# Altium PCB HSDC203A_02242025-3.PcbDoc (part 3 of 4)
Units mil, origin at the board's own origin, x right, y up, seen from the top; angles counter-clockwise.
Board outline 5612.98 x 3012.39 mil, 6 copper layers (Top Layer, GND1, Signal1, Power, GND2, Bottom Layer), stack 60.4 mil thick; 301 components, 211 nets, 1107 pads, 249 vias.
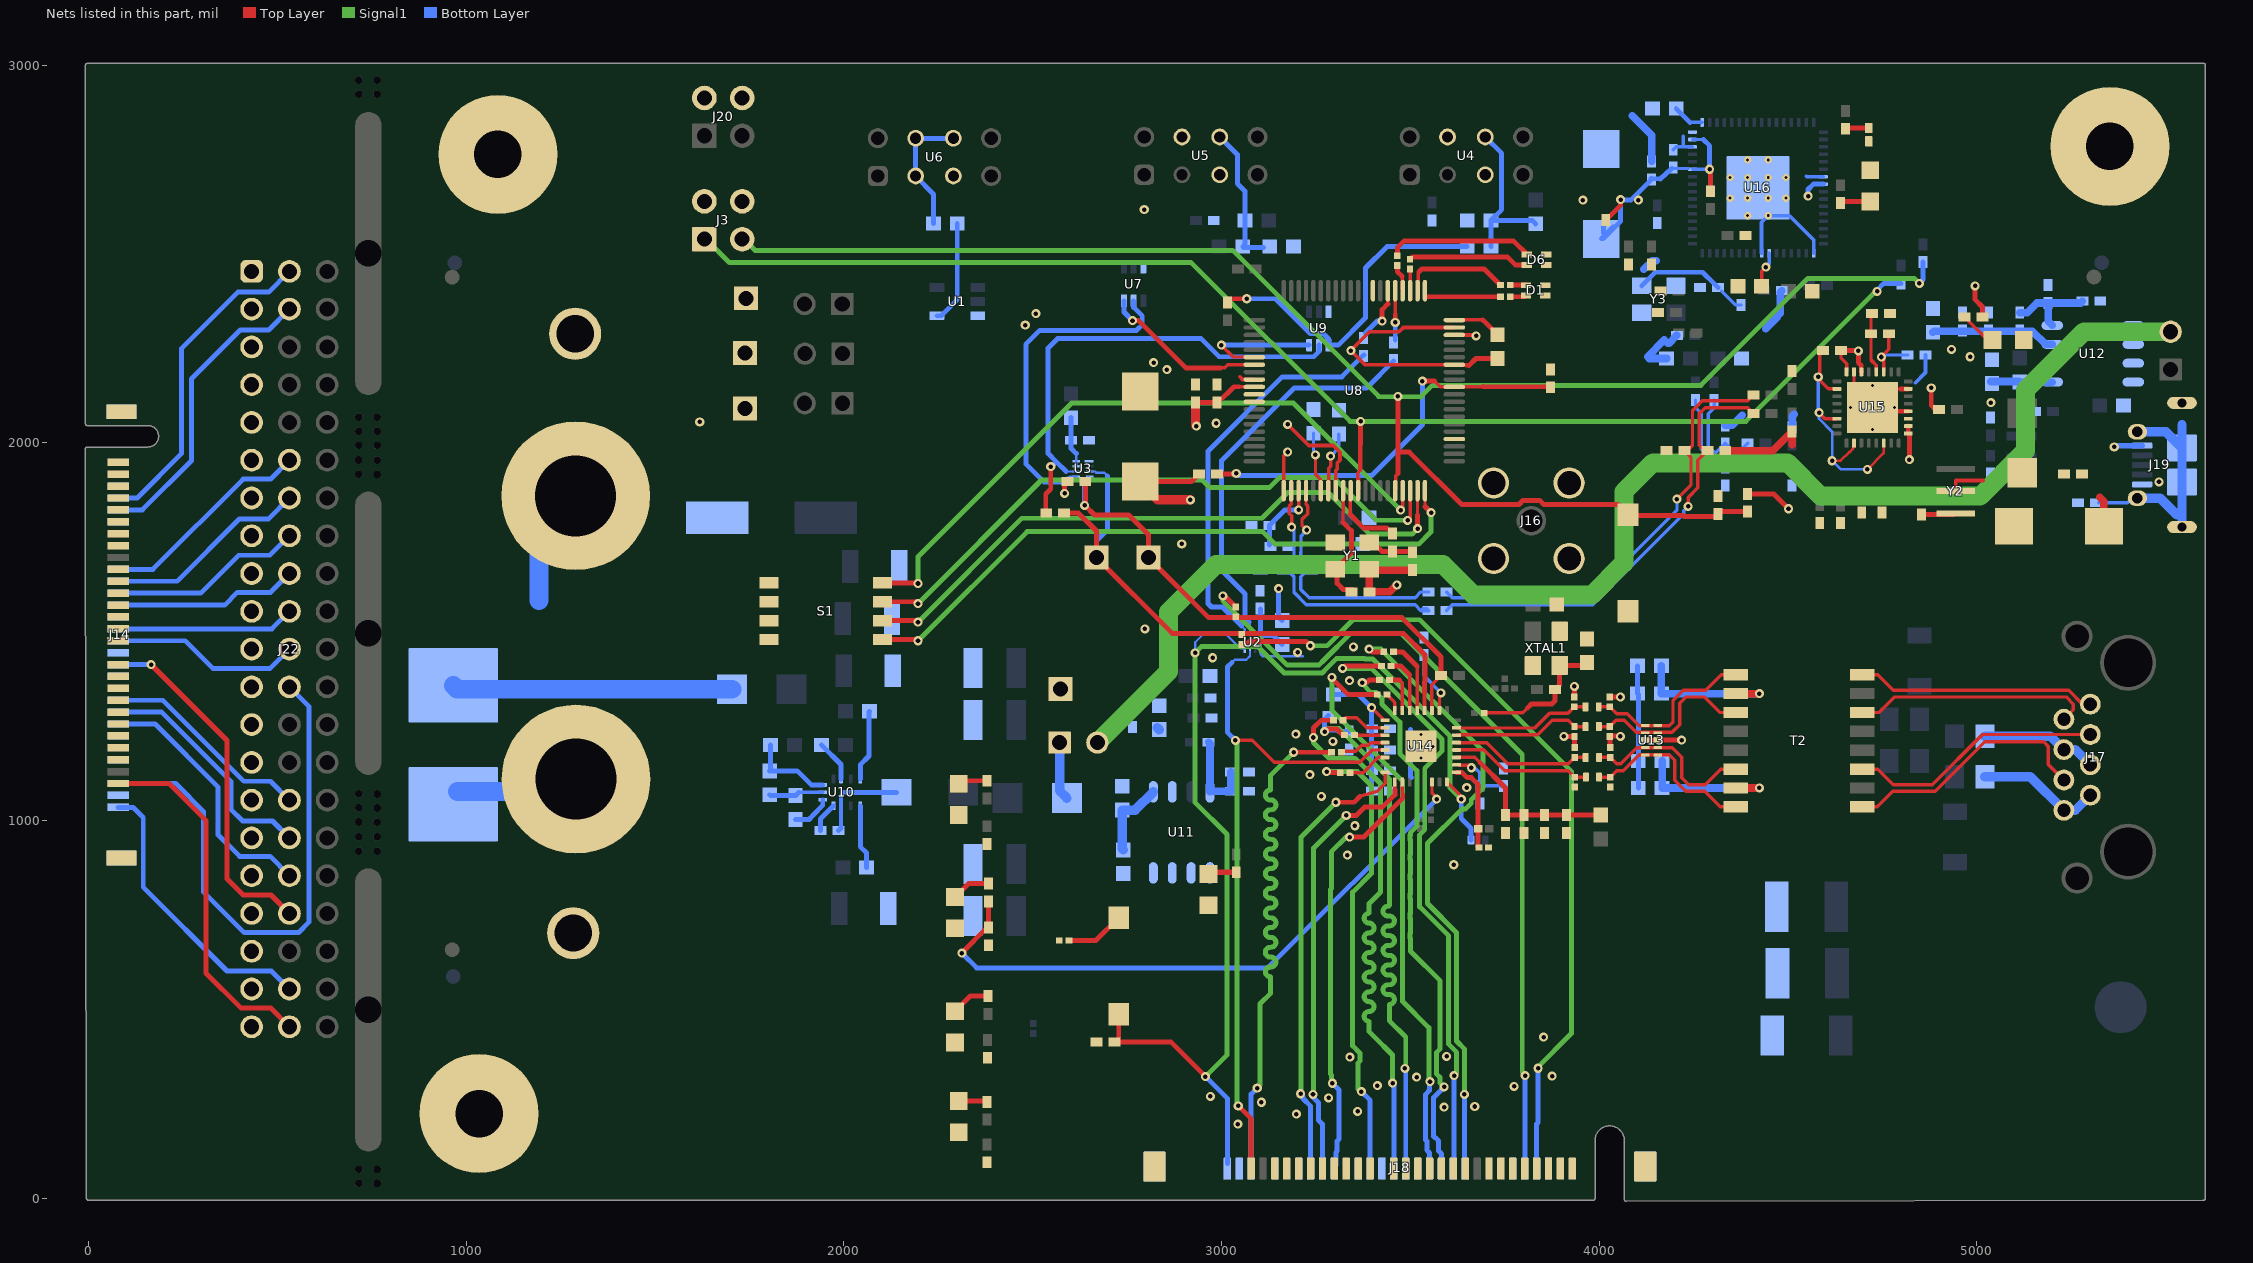
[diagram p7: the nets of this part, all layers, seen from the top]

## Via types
v1: diameter 24, hole 12, Top Layer to Bottom Layer, tented both sides, 227 vias
v2: diameter 19.68, hole 7.87, Top Layer to Bottom Layer, 17 vias
v3: diameter 19.68, hole 7.87, Top Layer to Bottom Layer, tented both sides, 5 vias

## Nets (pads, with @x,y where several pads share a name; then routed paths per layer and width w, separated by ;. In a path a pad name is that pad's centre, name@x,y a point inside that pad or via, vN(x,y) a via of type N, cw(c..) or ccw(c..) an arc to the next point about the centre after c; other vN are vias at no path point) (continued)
GND: C1.2 C2.2 C3.2 C4.2 C5.2 C6.2 C7.2 C8.2 C9.2 C10.2 C11.1 C12.2 C13.2 C14.2 C15.2 C16.2 C17.1 C18.2 C19.2 C20.2 C21.2 C22.2 C24.2 C25.2 C26.2 C27.2 C28.2 C29.2 C30.2 C31.2 C32.2 C33.2 C34.2 C35.2 C36.2 C37.2 C38.2 C39.2 C40.2 C41.2 C42.2 C43.2 C44.2 C45.2 C46.2 C47.2 C48.2 C49.2 C50.2 C51.2 C52.2 C53.2 C54.2 C55.2 C56.2 C57.2 C60.2 C61.1 C62.2 C63.1 C64.2 C65.1 C66.2 C67.2 C68.2 C69.2 C70.1 C71.1 C72.2 C73.2 C74.2 C75.2 C76.2 C77.2 C78.2 C79.2 C80.2 C81.2 C82.2 C83.2 C84.2 C85.2 C86.2 C87.2 C89.2 C90.2 C91.2 C92.2 C93.2 C94.2 C95.2 C96.2 C97.2 C98.2 D1.3 D1.4 D4.1 D5.2 D6.3 D6.4 H1.1 H2.1 H3.1 J3.2 J3.4 J5.1 J10.1 J11.1 J12.1 J13.1 J16.2 J16.3 J16.4 J16.5 J18.1 J18.3 J18.5 J18.6 J18.7 J18.9 J18.11 J18.12 J18.13 J18.15 J18.19 J18.21 J18.23 J18.25 J18.27 J18.28 J18.29 J18.31 J18.34 J18.35 J18.37 J18.38 J18.39 J18.41 J18.43 J18.45 J18.47 J18.48 J18.49 J18.51 J18.52 J18.58 J18.MP1 J18.MP2 J18.MP3 J18.MP4 J19.5 J20.2 J20.4 J21.1 LD1.2 LD2.2 LD3.2 LD4.2 LD5.2 LD6.2 R12.1 R21.2 R26.1 R30.1 R31.1 R35.1 R36.1 R48.1 R49.1 R50.1 R51.2 R54.1 R56.2 R59.1 R60.1 R69.1 R70.1 R73.1 R74.1 R75.2 R81.1 R82.1 R83.1 R84.1 R85.1 R91.1 R92.1 R115.1 S1.5 S1.6 S1.7 S1.8 S2.1 U1.3 U2.1 U3.1 U4.3 U4.7 U5.3 U5.7 U6.3 U7.3 U8.14 U8.19 U8.49 U8.61 U8.68 U9.3 U10.1 U10.6 U10.11 U11.5 U11.6 U11.7 U11.8 U12.5 U12.6 U12.7 U12.8 U13.3@4122.24,1213.15 U13.8@4155.12,1213.15 U14.33 U15.7 U15.27 U15.28 U15.31 U15.33 U16.14 U16.16 U16.39 U16.49 U16.56 U16.65 XTAL1.2 XTAL1.4 Y1.2 Y1.4 Y2.2 Y3.2 Y3.4 | length 4770.6
  Top Layer w9: U15.7@4674.52,2188.42 4674.52,2143.14 v2(4723.73,2093.93)
  Top Layer w10: 3048.53,2175.2 3055.75,2167.98 U8.49@3086.92,2167.98 U8.49@3086.92,2168.23 ; U8.61@3164.67,1873.69 3164.67,1965.87 v1(3174.9,1976.1) ; v1(3174.9,2049.48) 3231,1993.38 3295.81,1993.38 3313.85,1975.33 3313.85,1954.73 3306.35,1947.23 3306.35,1931.03 3302.47,1927.15 U8.68@3302.47,1873.69 ; U8.14@3616.45,2206.44 3648.58,2206.44 3648.58,2204.72 3654.83,2204.72 3652.21,2207.35 U8.14@3616.45,2207.35 3379.77,2207.35 v1(3342.34,2244.78) 3391.95,2294.4 3470.25,2294.4 3481.63,2305.77 U8.19@3616.45,2305.77 ; Y2.2@4944.01,1872.28 4944.01,1900.9 5000.52,1900.9 5016.1,1900.9
  Top Layer w13: 3654.83,2204.72 3673.76,2223.66 C10.2@3731.07,2223.66 ; v1(3906.58,1223.19) C93.2@3934.63,1223.19 3935.04,1222.78 C95.2@3935.04,1193.47 ; C89.2@3934.22,1327.46 v1(3934.22,1355.51) ; C96.2@4028.12,1194.29 C94.2@4028.12,1223.19 ; C92.2@4028.12,1327.46 v1(4056.17,1327.46) ; C94.2@4028.94,1224.02 v1@4055.35,1224.02 ; U13.3@4122.24,1213.15 U13.8@4155.12,1213.15 v1(4218.39,1213.15) ; v2(4723.73,2093.93) 4733.57,2084.09 U15.28@4818.22,2084.09 ; 4797.1,2143.2 4797.16,2143.14 U15.31@4818.22,2143.14
  Top Layer w20: v1(3464.18,1624.02) 3445.82,1605.66 3391.39,1605.66 Y1.4@3391.39,1665.53 3393.36,1663.56 C8.2@3505.51,1663.56 ; R69.1@4333.77,1979.56 4459.75,1979.56 C68.2@4510.93,2030.74 4510.93,1995.31 ; 5325.73,1855.94 5336.07,1845.6 C64.2@5336.07,1779.04
  Bottom Layer w6: U2.1@3102.95,1456.3 3102.95,1440.55 3108.3,1435.21 3214.97,1435.21
  Bottom Layer w9: C87.2@4195.97,2776.21 4203.53,2783.78 4225.2,2783.78 ; 4222.75,2812.15 4222.75,2786.22 4225.2,2783.78 ; U16.14@4246.94,2783.78 4225.2,2783.78 ; 4548.12,2706 4549.08,2705.04 U16.39@4593.39,2705.04
  Bottom Layer w10: C26.2@1881,1075 U10.6@1944.28,1075 ; U16.56@4430.01,2502.28 4430.01,2584.17 v2(4447.53,2601.69) 4503.39,2601.69 4567.8,2537.28 U16.49@4567.8,2502.28 ; 4837.03,2159.48 4863.78,2186.23 C77.2@4863.78,2232.88
  Bottom Layer w13: R26.1@1803.78,1068.75 1806.34,1066.19 C26.2@1872.19,1066.19 C26.2@1881,1075 ; U10.1@2043.69,1039.56 2043.69,931.17 2060.48,914.39 2060.48,875.76 C22.2@2060.43,875.7 ; U10.11@2043.69,1110.43 2043.69,1148.31 2066.73,1171.35 2066.73,1288.48 C20.2@2067.83,1289.57 ; 3500.71,1241.37 3500.71,1116.63 3503.54,1113.8 ; C45.2@4101.54,1410.13 C46.2@4101.54,1336.54 4103.45,1334.62 C55.2@4103.45,1158.23 C56.2@4103.45,1086.54
  Bottom Layer w20: 4088,2866 4138.89,2815.11 C86.2@4138.89,2745.31 ; 4118.39,2459.57 4141.11,2482.29 4150.7,2482.29 ; 4172.66,2272.89 4128,2228.24 4132.58,2223.66 C75.2@4178.55,2223.66 ; 4181.37,2264.18 4185.25,2264.18 R81.1@4205.75,2284.68 ; R74.1@4333.77,2046.49 4351.91,2046.49 4378.37,2072.95 ; 4441.45,2302.71 4471.21,2332.48 4471.21,2336.42 4478.71,2343.92 4478.71,2399.05 C91.2@4483.16,2403.49 ; C73.2@4510.93,2042.55 4510.93,2070.79 4516.16,2076.02
  Bottom Layer w50: 1192.52,1582.71 1192.52,1790.19 J21.1@1251.57,1849.25
  other v1: 3043.58,196.52 3198.43,223.38 3360.6,230.28 3589.14,241.73 3670.45,243.31 3105.71,254.57 3283.63,266.11 2970.51,270.04 3774.94,296.33 3412.43,298.46 3516.65,321.11 3875.03,323.88 3339.8,374.02 3596.08,375.94 3852.73,426.8 3614.79,883.31 3333.22,908.7 3352.94,986.57 3264.29,1064.13 3649.34,1087.43 3234.16,1121.89 3294.96,1209.99 4056.17,1223.19 3197.17,1229.42 3338.89,1371.06 2976.67,1431.3 3201.55,1445.78 3348.87,1460.19 2797.29,1507.84 2894.81,1732.92 5482,1897 2985.67,2052.31 1618.66,2055.59 5037.01,2106.69 2855.2,2194 2820.14,2212.83 2480.36,2311.94 2508.7,2342.61 2795.44,2617.86
  other v2: 4723.73,2035.86 4665.66,2093.93 4781.8,2093.93 4723.73,2152 4392.8,2601.69 4346.34,2648.15 4392.8,2648.15 4447.53,2648.15 4493.98,2648.15 4346.34,2702.87 4392.8,2702.87 4447.53,2702.87 4493.98,2702.87 4392.8,2749.33 4447.53,2749.33
  other v3: 3527.82,1165.52 3496.33,1197.01 3527.82,1197.01 3559.32,1197.01 3527.82,1228.51
GND_EXT: J14.1 J14.3 J14.5 J14.6 J14.7 J14.9 J14.11 J14.12 J14.13 J14.15 J14.19 J14.21 J14.23 J14.25 J14.27 J14.28 J14.29 J14.31 J14.34 J14.35 J14.37 J14.38 J14.39 J14.41 J14.43 J14.45 J14.47 J14.48 J14.49 J14.51 J14.52 J14.58 J14.MP1 J14.MP2 J14.MP3 J14.MP4 J22.1 J22.4 J22.7 J22.10 J22.13 J22.16 J22.19 J22.22 J22.25 J22.28 J22.31 J22.34 J22.37 J22.40 J22.43 J22.46 J22.49 J22.52 J22.55 J22.58 J22.61
HUB_D1_N: R63.2 R67.1 R70.2 | length 1191
  Top Layer w9: v1(4205.82,1851.61) 4242.87,1888.66 4242.87,1962.19 R70.2@4225.5,1979.56 4230,1984.06 4237.26,1984.06 4247.01,1993.82 4247.01,2085.53 4273.08,2111.59 4392.97,2111.59 R67.1@4408.57,2127.2 R67.1@4408.46,2127.31
  Bottom Layer w9: R63.2@3595.58,1605.55 3611.19,1589.94 3973.67,1589.94 4205.82,1822.08 v1(4205.82,1851.61)
HUB_D1_P: R66.2 R68.1 R69.2 | length 1193.6
  Top Layer w9: v1(4235.34,1831.92) 4235.34,1855.68 4260.87,1881.21 4260.87,1953.91 R69.2@4286.52,1979.56 4282.02,1984.06 4274.77,1984.06 4265.01,1993.82 4265.01,2078.07 4280.54,2093.59 4392.97,2093.59 R68.1@4408.57,2077.99
  Bottom Layer w9: R66.2@3595.58,1556.33 3611.19,1571.94 3982.82,1571.94 4223.82,1812.94 ; 4223.82,1814.63 4223.82,1820.4 v1(4235.34,1831.92)
HUB_D2_N: R71.1 R74.2 R76.2 | length 268.5
  Bottom Layer w9: R76.2@4304.24,2113.42 4304.24,2093.17 4288.64,2077.57 4288.64,1991.18 4304.04,1975.77 4310.29,1975.77 R74.2@4333.77,1999.25 4357.25,1975.77 4369.15,1975.77 R71.1@4392.82,1999.44
HUB_D2_P: R72.1 R73.2 R80.2 | length 292.7
  Bottom Layer w9: R80.2@4255.03,2113.42 4255.03,2093.17 4270.64,2077.57 4270.64,1983.72 4296.59,1957.77 4310.29,1957.77 R73.2@4333.77,1934.29 4357.25,1957.77 4369.69,1957.77 4379.58,1947.88 R72.1@4392.82,1947.88
LED_0: R54.2 R55.1 U14.30 | length 1679.4
  Top Layer w9: U14.30@3557.35,1102.52 3557.39,1072.4 3571.71,1058.08 3570.87,1057.24 v1(3569.72,1057.24)
  Top Layer w13: v1(2312.37,649.61) 2380.26,717.49 R54.2@2383.24,717.49 R55.1@2383.24,786.39
  Bottom Layer w13: v1(2312.37,649.61) 2351.74,610.24 3122.72,610.24 v1(3569.72,1057.24)
MCU_VCC: C13.1 C14.1 C15.1 C39.1 C40.1 C41.1 C77.1 C85.1 C86.1 C87.1 R1.2 R22.1 R23.1 R33.2 R34.2 R61.2 R62.2 R79.2 R90.2 R93.2 U8.18 U8.50 U12.3 U15.3 U15.6 U15.8 U15.25 U15.26 U16.11 U16.15 U16.40 | length 2510.9
  Top Layer w9: 3046.32,2148.85 U8.50@3086.92,2148.85 ; R62.2@4649.63,2245.23 4640.23,2235.83 4640.23,2223.85 4654.83,2209.25 U15.8@4654.83,2188.42 ; U15.3@4753.26,2188.42 4753.26,2221.19 v1(4746.86,2227.59) 4766.84,2247.57 R79.2@4766.84,2289.18
  Top Layer w10: U8.18@3616.45,2286.65 3617.35,2285.74 3671.93,2285.74 v1(3674.21,2283.46)
  Top Layer w13: C13.1@2784.75,1895.89 C13.1@2784.75,1897.97 2921.16,1897.97 R23.1@2940.55,1917.36 ; v1@2931.18,2046.95 v1(2933.41,2044.72) ; C15.1@2931.18,2107.62 C14.1@2987.94,2107.62 2991.84,2107.62 3033.07,2148.85 3046.32,2148.85 ; R90.2@4017.32,2590.11 4056.69,2629.48 v1(4056.69,2644.16) ; v1(4292.21,2724.72) 4294.4,2722.53 R93.2@4294.4,2666.57 ; R22.1@4392.82,1865.39 4461.56,1865.39 v1(4501.09,1825.86) ; R62.2@4640.23,2245.23 4649.63,2245.23 4684.47,2245.23 v1(4686.07,2243.62) 4686.07,2212.77 4693.81,2205.03 4693.81,2188.81 U15.6@4694.2,2188.42 ; U15.26@4818.22,2044.72 U15.25@4818.22,2025.03 4821.17,2022.08 v1(4821.17,1955.8) ; v1(4879.04,2145.67) 4879.04,2099.76 R61.2@4890.22,2088.58 ; v1(4995.19,2415.9) 4995.19,2379.49 5014.72,2359.96 R34.2@5014.72,2333.36
  Top Layer w25: C13.1@2784.75,1895.89 2831.2,1849.44 v1(2917.38,1849.44) ; v1@2931.18,2046.95 C15.1@2931.18,2107.62
  Bottom Layer w9: C87.1@4192.42,2726.6 U16.11@4236.45,2726.6 ; U16.11@4246.94,2724.72 v1(4292.21,2724.72) ; U16.15@4246.94,2803.46 4275.69,2803.46 ; v1(4746.86,2227.59) 4752.15,2232.88 C77.1@4816.54,2232.88
  Bottom Layer w13: v1(3151.18,1614.17) 3151.18,1539.27 R1.2@3160.92,1529.53 ; C85.1@4011.47,2556.03 C85.1@4011.47,2571.71 ; C85.1@4037.01,2572.02 C85.1@4005.57,2540.58 4010.35,2540.58 4056.69,2586.93 4056.69,2642.95 4083.77,2642.95 C86.1@4138.89,2698.07 ; C86.1@4137.06,2700.08 4138.98,2699.98 4161.78,2698.85 C87.1@4192.42,2726.6 ; 4275.69,2803.46 4292.21,2786.94 v1(4292.21,2724.72) ; v1(4552.81,2653.76) 4552.81,2671.04 4567.12,2685.35 U16.40@4593.39,2685.35
  Bottom Layer w20: C41.1@4883.46,2293.31 4886.48,2296.33 5146.76,2296.33 5181.86,2261.22 U12.3@5199.41,2261.22
  other v1: 4981.89,2228.24 4932.68,2247.57 3956.51,2643.24 4103.45,2643.24
MDC: J1.1 R18.1 R109.1 U3.3 U14.12 | length 1579.9
  Top Layer w10: U14.12@3537.67,1291.5 3537.71,1338.58
  Top Layer w13: R109.1@2583.27,1814.44 2621.5,1814.44 2668.9,1767.04 2668.9,1720.85 J1.1@2685.56,1704.19 ; J1.1@2668.9,1696.58 2869.42,1496.06 3481.37,1496.06 3538.9,1438.53 3538.9,1368.86 3537.77,1367.73 3537.77,1338.64 3537.71,1338.58
  Bottom Layer w6: U3.3@2651.18,1924.44 2651.44,1924.19 2665.32,1924.19 2668.25,1921.26 2689.9,1921.26 2698.43,1912.74
  Bottom Layer w13: J1.1@2668.9,1696.58 2668.9,1741.32 2698.43,1770.84 2698.43,1912.74
MDC_EXT: J14.8 J22.2 | length 865.1
  Bottom Layer w13: J14.8@78.74,1854.33 128.88,1854.33 247.01,1972.46 247.01,2250.74 395.52,2399.25 477.17,2399.25 J22.2@532.28,2454.36
MDC_LVL: R109.2 U3.6 U9.5 | length 1298
  Top Layer w13: R109.2@2536.02,1814.44 2534.64,1815.82 2534.64,1864.95 2547.92,1878.23 v1(2547.92,1937.45)
  Bottom Layer w6: 2588.55,1924.44 U3.6@2615.75,1924.44
  Bottom Layer w13: v1@2543.34,1935.44 2546.84,1935.44 2562.2,1950.79 ; 2588.55,1924.44 2562.2,1950.79 ; U9.5@3257.7,2258.86 3257.7,2241.48 3244.54,2228.33 3239.85,2228.33 3239.76,2228.24 3239.68,2228.33 2993.8,2228.33 2945.89,2276.24 2565.74,2276.24 2540.94,2251.44 2540.94,1972.05 2562.2,1950.79
MDC_MSP: U8.46 U9.6 | length 332.5
  Top Layer w9: v1(2999.75,2258.86) 3031.02,2227.59 U8.46@3086.92,2227.59
  Bottom Layer w13: v1(2999.75,2258.86) U9.6@3232.11,2258.86
MDC_S: J18.8 R18.2 | length 2154.6
  Top Layer w13: R18.2@3053.74,1466.54 3056.3,1469.09 3067.96,1469.09 3073.42,1474.55 3224.02,1474.55 v1(3235.34,1463.22)
  Signal1 w13: v1(3235.34,1463.22) 3279.57,1463.22 3348.28,1531.93 3524.73,1531.93 3926.24,1130.43 3926.24,436.48 v1@3834.25,344.5
  Bottom Layer w13: J18.8@3838.39,92.66 3834.25,96.8 3834.25,196.85 3838.39,200.98 v1(3838.39,344.5)
MDIO: J2.1 R19.1 R47.1 R110.1 U3.4 U14.11 | length 1435.8
  Top Layer w9: U14.11@3557.35,1291.5 3556.64,1292.25 3556.64,1359.91 R47.1@3581.01,1384.29
  Top Layer w13: R110.1@2639.37,1897.87 2639.37,1833.52 2663.68,1809.2 2754.21,1809.2 2806.69,1756.72 J2.1@2806.69,1696.58 2965.77,1537.51 3477.47,1537.51 3581.01,1433.96 R47.1@3581.01,1384.29
  Bottom Layer w13: v1(2637.4,1835.02) 2637.4,1895.83 2647.77,1906.2 2647.24,1906.73
MDIO_EXT: J14.10 J22.5 | length 800.9
  Bottom Layer w13: J14.10@78.74,1822.83 143,1822.83 273.16,1953 273.16,2170.12 402.3,2299.25 477.17,2299.25 J22.5@532.28,2354.36
MDIO_LVL: R110.2 U3.5 U7.5 | length 944.9
  Top Layer w13: v1(2584.68,1866.58) 2584.68,1890.43 R110.2@2592.13,1897.87
  Bottom Layer w6: 2580.32,1896.86 2591.1,1907.64 2595.51,1907.64 2598.53,1910.66 U3.5@2615.75,1910.66
  Bottom Layer w13: v1(2584.68,1866.58) 2584.68,1892.49 2580.32,1896.86 2529.65,1896.86 2481.89,1944.62 2481.89,2261.22 2518.91,2298.24 2775,2298.24 2790.11,2313.36 2790.11,2336.41 2767.32,2359.2 U7.5@2767.32,2376.57
MDIO_MSP: U7.6 U8.47 | length 439.8
  Top Layer w9: 2997.84,2198.93 3008.44,2198.93 3016.86,2207.35 U8.47@3086.92,2207.35
  Top Layer w13: v1(2764.31,2324.04) 2780.45,2324.04 2905.56,2198.93 2997.84,2198.93
  Bottom Layer w13: U7.6@2741.73,2376.57 2741.73,2346.62 v1(2764.31,2324.04)
MDIO_S: J18.10 R19.2 | length 2188.5
  Top Layer w13: v1(3003.54,1594.92) 3008.57,1594.92 R19.2@3037.71,1565.78
  Signal1 w13: v1@3805.81,324.8 3796.17,334.44 3796.17,1175.12 3475.23,1496.06 3341.93,1496.06 3272.59,1426.72 3257.64,1411.77 3174.4,1411.77 3003.54,1582.62 ; 3003.54,1582.62 v1(3003.54,1594.92) 3003.54,1582.62
  Bottom Layer w13: J18.10@3803.91,92.66 v1(3803.91,324.8)
MSP_PWDN: R10.2 U8.25 | length 131.5
  Top Layer w9: 3459.95,2340.58 U8.25@3459.95,2403.77
  Top Layer w13: v1(3459.95,2319.27) 3459.95,2340.58
  Bottom Layer w13: R10.2@3459.95,2272.31 v1(3459.95,2319.27)
MSP_RESET: R11.2 U8.26 | length 144.2
  Top Layer w9: 3440.27,2368.3 U8.26@3440.27,2403.77
  Top Layer w13: v1(3425.11,2322.83) 3425.11,2353.14 3440.27,2368.3
  Bottom Layer w13: R11.2@3381.21,2291.34 3412.71,2322.83 v1(3425.11,2322.83)
MSP_XIN: C7.1 U8.69 Y1.3 | length 313.3
  Top Layer w9: 3321.56,1790.51 3321.56,1818.4 3322.15,1818.99 U8.69@3322.15,1874.25
  Top Layer w13: 3321.56,1790.51 3343.98,1768.1 3343.98,1714.54 ; 3343.8,1708.24 3306.01,1670.45 3306.01,1628.22 3322.15,1612.08 C7.1@3347.75,1612.08
MSP_XOUT: R13.2 U8.70 | length 197.1
  Top Layer w9: 3340.43,1810.58 3340.43,1872.84 U8.70@3341.84,1874.25
  Top Layer w13: 3340.43,1810.58 3375.67,1775.34 3437.04,1775.34 R13.2@3452.37,1760.02
NetC3_1: C3.1 R3.1 R6.2 U4.6 | length 441.9
  Bottom Layer w13: U4.6@3698.34,2810.17 3741.73,2766.77 3741.73,2617.59 C3.1@3713.55,2589.41 ; R6.2@3713.55,2519.98 C3.1@3713.55,2589.41 ; R3.1@3831.8,2580.25 3822.64,2589.41 C3.1@3713.55,2589.41
NetC4_1: C4.1 R4.1 R7.2 U5.6 | length 376.9
  Bottom Layer w13: U5.6@2995.28,2810.17 3041.8,2763.65 3041.8,2687.01 3062.07,2666.73 R4.1@3062.07,2588.81 3062.07,2525.82 R7.2@3056.17,2519.91 3058.36,2517.72 C4.1@3111.81,2517.72
NetC5_1: C5.1 R1.1 U2.7 U2.8 | length 148.3
  Bottom Layer w13: 3092.92,1489.76 U2.8@3102.95,1489.76 ; C5.1@3102.95,1560.44 U2.8@3102.95,1489.76 ; R1.1@3160.92,1466.54 3137.69,1489.76 U2.8@3102.95,1489.76
NetC6_1: C6.1 R2.1 U3.7 U3.8 | length 134.4
  Bottom Layer w6: U3.7@2615.75,1938.22 2615.75,1941.67 2615.75,1948.56 U3.8@2615.75,1952 2615.75,1971.69
  Bottom Layer w13: R2.1@2601.97,2066.93 C6.1@2601.97,2007.12 2601.97,1985.47 2615.75,1971.69
NetC8_1: C8.1 R13.1 Y1.1 | length 121.6
  Top Layer w13: Y1.1@3396.56,1741.32 3425.11,1712.77 R13.1@3452.37,1712.77 3503.54,1712.77 C8.1@3505.51,1710.8
NetC9_1: C9.1 U8.67 | length 161
  Top Layer w9: U8.67@3282.78,1874.25 3284.19,1875.65 3284.19,1933.44 3288.98,1938.22 v1(3288.98,1965.03)
  Bottom Layer w9: v1(3288.98,1965.03) 3310.86,1986.91 C9.1@3310.86,2023.62
NetC10_1: C10.1 U8.20 | length 126.2
  Top Layer w9: U8.20@3616.45,2326.02 3691.17,2326.02
  Top Layer w13: 3691.17,2326.02 3720.38,2296.8 C10.1@3720.38,2286.65
NetC12_1: C12.1 U8.66 | length 160.7
  Top Layer w9: v1(3248.79,1968.5) v1@3248.79,1964.07 ; v1@3249.61,1963.25 v1@3248.79,1964.07 ; U8.66@3263.1,1874.25 3261.69,1875.65 3261.69,1904.46 3248.79,1917.36 v1@3248.79,1964.07
  Bottom Layer w9: C12.1@3243.41,2025.59 3243.41,1973.88 v1(3248.79,1968.5)
NetC16_1: C16.1 R23.2 U8.11 | length 1064.3
  Top Layer w9: 3564.38,2163.56 3579.09,2148.85 3691.8,2148.85 3692.52,2149.58 ; C16.1@3869.99,2148.85 C16.1@3871.17,2147.67
  Top Layer w13: R23.2@2987.8,1917.36 3037.04,1917.36 v1(3038.98,1919.29) ; v1(3532.02,2163.56) 3564.38,2163.56 ; 3692.52,2149.58 C16.1@3869.99,2148.85
  Bottom Layer w13: v1(3038.98,1919.29) 3044.42,1913.85 3397.55,1913.85 3532.02,2048.32 v1(3532.02,2163.56)
NetC23_1: C23.1 U10.4 | length 80.2
  Bottom Layer w13: C23.1@1938.31,973.67 1938.31,1005.04 U10.4@1972.83,1039.56
NetC23_2: C23.2 L1.1 U10.3 U10.12 | length 246.5
  Bottom Layer w10: C23.2@1992.51,980.63 U10.3@1992.51,1039.56 1992.51,1067.2 U10.12@2000.31,1075
  Bottom Layer w13: C23.2@1985.55,973.67 C23.2@1992.51,980.63 ; U10.12@2000.31,1075 U10.12@2030.43,1075 L1.1@2139.37,1075
NetC26_1: C26.1 U10.5 | length 102.9
  Bottom Layer w13: C26.1@1872.19,1003.2 1907.92,1003.2 1917.43,1012.71 1917.43,1013.69 1944.28,1040.54 U10.5@1944.28,1055.31
NetC36_1: C36.1 R28.1 R31.2 U11.4 | length 240
  Bottom Layer w20: R28.1@2965.79,1207.64 2969.53,1203.9 U11.4@2969.53,1076.34 2971.18,1078 R31.2@3025.13,1078 C36.1@3025.13,1128.9
NetC42_1: C42.1 R33.1 R36.2 U12.4 | length 242.6
  Bottom Layer w20: R33.1@5113.3,2344.95 5133.38,2344.95 5159.08,2370.64 R36.2@5188.5,2370.64 ; U12.4@5199.41,2311.22 5188.5,2322.13 R36.2@5188.5,2370.64 ; C42.1@5279.33,2375.54 5274.43,2370.64 R36.2@5188.5,2370.64
NetC43_1: C43.1 R37.1 R39.2 XTAL1.3 | length 375.2
  Top Layer w9: R37.1@3695.67,1285.05 3695.67,1286.09 3797.63,1286.09 3810.33,1298.79
  Top Layer w13: 3810.33,1298.79 3820.59,1309.06 3874.68,1309.06 3882.98,1317.36 R39.2@3882.98,1347.04 3895.28,1359.34 XTAL1.3@3895.28,1411.02 3959.79,1411.02 C43.1@3967.27,1418.5
NetC45_1: C45.1 C46.1 T2.2 | length 396
  Top Layer w20: T2.2@4360.97,1336.54 4423.86,1336.54 v1(4423.95,1336.45)
  Bottom Layer w20: C45.1@4164.53,1410.13 C46.1@4164.53,1336.54 v1@4423.95,1336.54
NetC47_1: C47.1 C48.1 C51.1 C52.1 R41.1 U14.3 | length 486.7
  Top Layer w9: U14.3@3622.31,1167.48 3670.82,1167.48 3683.76,1154.54
  Top Layer w13: 3683.76,1154.54 3751.85,1086.45 C51.1@3751.85,1014.98 C47.1@3801.17,1014.98 C52.1@3855.25,1014.98 C48.1@3912.99,1014.98 R41.1@4003.95,1014.98
NetC49_1: C49.1 C50.1 C53.1 C54.1 R88.2 U14.17 | length 393.2
  Top Layer w9: v1@3402.04,1295.04 3397.86,1299.21 v1(3397.24,1299.21) 3431.16,1265.91 U14.17@3433.38,1265.91
  Bottom Layer w13: R88.2@3296.06,1334.18 3362.26,1334.18 v1(3397.24,1299.21) 3397.24,1243.5 3397.24,1187.17 3397.24,1132.14 3397.24,1080.29 C50.1@3398.87,1078.66
NetC55_1: C55.1 C56.1 T2.7 | length 392.8
  Top Layer w20: T2.7@4360.97,1086.54 4424.06,1086.54 v1(4424.25,1086.73)
  Bottom Layer w20: C55.1@4166.45,1158.23 C56.1@4166.45,1086.54 v1@4424.25,1086.54
NetC57_1: C57.1 C62.1 U14.2 | length 170.4
  Top Layer w9: U14.2@3627.51,1146.88 3663.46,1146.88 3661.43,1144.85 v1(3661.43,1140.17)
  Bottom Layer w9: v1(3661.43,1140.17) 3667.06,1140.17 3668.61,1141.73 3683.86,1126.49 C57.1@3683.86,1092.37 3745.84,1092.37 C62.1@3746.85,1091.36
NetC64_1: C64.1 C65.2 D7.2 J19.1 | length 75.5
  Bottom Layer w15: v1(5363.49,1989.43) 5366.95,1992.89 J19.1@5437.6,1992.89
NetC74_1: C74.1 R79.1 U15.4 | length 161.1
  Top Layer w9: C74.1@4722.35,2342.61 4719.6,2339.85 R79.1@4719.6,2289.18 4719.6,2219.67 4733.57,2205.69 U15.4@4733.57,2188.42
NetC81_1: C81.1 U16.55 | length 106.3
  Top Layer w9: C81.1@4434.53,2423.99 4434.53,2419.52 C81.1@4430.01,2414.99 4430.01,2454.32 v1(4441.45,2465.76)
  Bottom Layer w9: v1(4441.45,2465.76) 4449.69,2474.01 U16.55@4449.69,2502.28
NetC82_1: C82.1 U16.17 | length 83.7
  Bottom Layer w9: 4240.18,2848.74 U16.17@4272.53,2848.74
  Bottom Layer w13: C82.1@4203.85,2885.07 4240.18,2848.74
NetC90_1: C90.1 R38.1 Y3.1 | length 299.8
  Bottom Layer w9: C90.1@4324.35,2401.57 4360.51,2365.42 R38.1@4375.6,2365.42
  Bottom Layer w13: Y3.1@4112.62,2415.9 4148.8,2452.08 4273.57,2452.08 4287.9,2437.75 4288.54,2437.75 4314.08,2412.21 C90.1@4314.08,2411.56
NetD1_1: D1.1 R15.1 | length 41.9
  Top Layer w13: R15.1@3764.57,2418.06 3805.7,2418.06 D1.1@3806.21,2417.55
NetD1_2: D1.2 R14.1 | length 42.9
  Top Layer w13: R14.1@3764.57,2387.06 3803.27,2387.06 D1.2@3806.21,2389.99
NetD2_2: D2.2 XF1.1 | length 742
  Bottom Layer w50: XF1.1@966.14,1358.27 976.34,1348.07 D2.2@1703.94,1348.07
NetD3_1: D3.1 J6.1 | length 155
  Bottom Layer w25: J6.1@2571.4,1206.85 2571.4,1079.08 D3.1@2590.63,1059.85
NetD4_2: D4.2 R86.1 | length 62.7
  Top Layer w9: R86.1@4652.04,2831.92 R86.1@4654.01,2833.89
  Top Layer w13: R86.1@4654.01,2833.89 D4.2@4713.89,2833.89
NetD5_1: D5.1 R87.1 | length 87.1
  Top Layer w9: D5.1@4713.4,2635.07 D5.1@4717.63,2639.3
  Top Layer w13: R87.1@4638.26,2635.07 4642.49,2639.3 D5.1@4717.63,2639.3
NetD6_1: D6.1 R17.1 | length 386.2
  Top Layer w13: R17.1@3465.59,2495.84 3465.59,2517.34 3482.63,2534.37 3773.51,2534.37 D6.1@3808.66,2499.23
NetD6_2: D6.2 R16.1 | length 320.5
  Top Layer w13: R16.1@3499.32,2486.61 3505.35,2492.65 3756.67,2492.65 3777.65,2471.67 D6.2@3808.66,2471.67
NetJ4_1: J4.1 J15.1 XF1.2 | length 247.8
  Bottom Layer w50: XF1.2@976.87,1077.61 1215.73,1077.61 J15.1@1222.05,1071.29
NetJ17_4: J17.4 J17.5 R45.2 | length 310.6
  Bottom Layer w25: R45.2@5021.01,1223.69 5194.57,1223.69 J17.4@5230.18,1188.08 5260.1,1188.08 J17.5@5300.26,1147.92
NetJ17_7: J17.7 J17.8 R46.2 | length 332.6
  Bottom Layer w25: R46.2@5021.01,1116.08 5141.55,1116.08 J17.8@5230.18,1027.45 5260.1,1027.45 J17.7@5300.26,1067.61
NetJ19_6: J19.6 J19.7 J19.8 J19.9 J19.10 J19.11 R75.1 | length 629.8
  Bottom Layer w9: R75.1@5322.43,1841.72 5398.74,1841.72 5404.94,1847.92 5411.26,1847.92 J19.6@5417.47,1841.72
  Bottom Layer w25: J19.6@5424.8,1854.11 5485.11,1854.11 5529.62,1809.61 ; J19.11@5424.8,2029.31 5500.59,2029.31 J19.9@5542.91,1986.98 ; J19.7@5542.91,1777.34 J19.8@5542.91,1896.43 J19.9@5542.91,1986.98 ; 5542.91,2048.06 J19.9@5542.91,1986.98
NetLD1_1: LD1.1 R29.1 | length 75.8
  Top Layer w15: LD1.1@2965.16,858.83 2969.9,863.57 R29.1@3038.98,863.57
NetLD2_1: LD2.1 R34.1 | length 99
  Top Layer w9: R34.1@4967.47,2333.36 5028.24,2272.59 LD2.1@5041.27,2272.59
NetLD3_1: LD3.1 R53.2 | length 78.3
  Top Layer w13: LD3.1@2304.5,1097.91 2312.37,1105.79 R53.2@2379.54,1105.79
NetLD4_1: LD4.1 R55.2 | length 103.4
  Top Layer w13: LD4.1@2294.65,797.86 2330.43,833.64 R55.2@2383.24,833.64
NetLD5_1: LD5.1 R57.2 | length 104
  Top Layer w13: LD5.1@2294.65,495.55 2334.89,535.78 R57.2@2382.01,535.78
NetLD6_1: LD6.1 R58.2 | length 75.9
  Top Layer w13: LD6.1@2304.27,257.6 2377.4,257.6 R58.2@2379.37,255.63
NetR5_1: R5.1 U6.2 U6.6 U6.7 | length 344.9
  Bottom Layer w13: R5.1@2237.47,2581.02 2237.47,2658.43 2190.15,2705.75 2190.15,2806.33 U6.6@2290.15,2806.33
NetR5_2: R5.2 U1.4 | length 273.5
  Bottom Layer w13: U1.4@2246.32,2336.92 2258.26,2336.92 2300.46,2379.12 R5.2@2300.46,2581.02
NetR24_1: R24.1 U10.9 | length 110.8
  Bottom Layer w13: R24.1@1941.33,1200.05 1992.51,1148.87 U10.9@1992.51,1110.43
NetR25_1: R25.1 R26.2 U10.7 | length 225.2
  Bottom Layer w12: R26.2@1803.78,1131.74 R26.2@1806.28,1134.24
  Bottom Layer w13: R26.2@1803.78,1131.74 1876.87,1131.74 1913.93,1094.68 U10.7@1944.28,1094.68 ; R26.2@1806.28,1134.24 R25.1@1806.28,1200.05
NetR27_1: R27.1 R30.2 U11.1 | length 208.9
  Bottom Layer w25: R30.2@2739.8,922.78 2737.05,925.53 R27.1@2737.05,1028.12 2771.3,1028.12 U11.1@2819.53,1076.34
NetR32_1: R32.1 R35.2 U12.1 | length 163.1
  Bottom Layer w20: R35.2@5037.01,2162.83 5112.37,2162.83 R32.1@5113.3,2161.9 5113.97,2161.22 U12.1@5199.41,2161.22
NetR49_2: R49.2 S3.1 | length 154.8
  Top Layer w13: R49.2@2598.26,682.71 2667.32,682.71 S3.1@2727.95,743.34
NetR50_2: R50.2 R105.1 U14.1 | length 237.1
  Top Layer w13: U14.1@3622.35,1128.01 3636.3,1128.01 3650.51,1113.8 3661.43,1113.8 3679.34,1095.89 R105.1@3679.34,978.33 R50.2@3679.34,929.12
NetR78_1: R78.1 U14.16 | length 51
  Top Layer w9: R78.1@3438.1,1333.89 3458.97,1313.03 U14.16@3458.97,1291.5
NetR98_1: R98.1 U14.22 | length 109.7
  Top Layer w9: R98.1@3340.39,1127.13 3375.04,1127.13 3415.4,1167.48 U14.22@3433.38,1167.48
NetR99_1: R99.1 U14.20 | length 116.1
  Top Layer w9: R99.1@3326.57,1184.29 3355.06,1184.29 3370.87,1200.09 3388.16,1200.09 3394.92,1206.85 U14.20@3433.38,1206.85
NetR100_1: R100.1 U14.13 | length 195.3
  Top Layer w9: U14.13@3517.98,1291.5 3518.02,1408.3
  Top Layer w13: R100.1@3455.62,1447.08 3479.24,1447.08 3518.02,1408.3
NetR101_1: R101.1 U14.14 | length 153.3
  Top Layer w9: U14.14@3498.3,1291.5 3498.34,1385.66
  Top Layer w13: R101.1@3449.12,1409.68 3474.32,1409.68 3498.34,1385.66
NetR102_1: R102.1 U14.15 | length 111
  Top Layer w9: 3471.83,1372.47 3478.65,1365.66 U14.15@3478.65,1291.5
  Top Layer w13: R102.1@3444.6,1372.47 3471.83,1372.47
NetR103_1: R103.1 U14.18 | length 125.3
  Top Layer w9: R103.1@3322.05,1265.91 3329.05,1272.91 3358.3,1272.91 3384.99,1246.22 U14.18@3433.38,1246.22
NetR104_1: R104.1 U14.19 | length 81.7
  Top Layer w9: R104.1@3351.68,1226.54 U14.19@3433.38,1226.54
NetR106_1: R106.1 Y2.3 | length 91.9
  Top Layer w9: Y2.3@4941.64,1813.22 Y2.3@4944.01,1813.22
  Top Layer w13: R106.1@4853.04,1810.86 4939.28,1810.86 Y2.3@4941.64,1813.22
OC_N: R62.1 U15.10 U15.14 U15.18 U15.22 | length 719
  Top Layer w7: v1(4616.65,1952.99) 4638.74,1952.99 4662,1976.26 4663.31,1976.26 4671.13,1984.07 4671.13,1985.38 4674.52,1988.77 U15.18@4674.52,1999.44 ; v1(4709.75,1929.97) 4753.26,1973.47 U15.22@4753.26,1999.44
  Top Layer w9: v1(4581.99,2080.15) 4597.73,2064.4 U15.14@4629.24,2064.4 ; R62.1@4602.82,2245.67 4583.77,2245.67 4583.77,2166.33 4606.96,2143.14 U15.10@4629.24,2143.14
  Bottom Layer w7: v1(4581.99,2080.15) 4581.99,2064.4 4616.65,2029.74 v1(4616.65,1952.99) 4639.67,1929.97 v1(4709.75,1929.97)
  Bottom Layer w9: v1(4579.83,2175.2) 4579.83,2082.3 v1(4581.99,2080.15)
P1.0: R14.2 U8.21 | length 194.7
  Top Layer w13: U8.21@3543.84,2387.06 R14.2@3738.58,2387.06
P1.1: R15.2 U8.22 | length 287
  Top Layer w9: U8.22@3520.41,2403.77 3520.41,2450.98 3522.75,2453.32
  Top Layer w13: 3522.75,2453.32 3530.06,2460.63 3696.01,2460.63 R15.2@3738.58,2418.06
P1.2: R16.2 U8.23 | length 56.9
  Top Layer w9: U8.23@3499.32,2403.77 R16.2@3499.32,2460.63
P1.3: R17.2 U8.24 | length 69.9
  Top Layer w9: U8.24@3478.23,2405.18 3478.23,2441.11
  Top Layer w13: R17.2@3465.59,2469.85 3465.59,2453.75 3478.23,2441.11
P1.7: U8.28
P4.4/UCA1TXD: U8.51
P4.5/UCA1RXD: U8.52
P6.7: U8.4
PWDN: J18.55 U2.3 U14.21 | length 1858.1
  Top Layer w9: v1(3036.94,1212.7) 3081.14,1212.7 3139.31,1154.54 3366.46,1154.54 3399.09,1187.17 U14.21@3433.33,1187.17
  Top Layer w13: v1(3044.25,244.92) 3078.35,210.82 J18.55@3078.35,92.66
  Signal1 w13: v1(3036.94,1212.7) 3041.2,1208.44 3041.2,247.96 v1(3044.25,244.92)
  Bottom Layer w6: 3028.01,1419.47 3034.94,1426.4 3065.47,1426.4 3075.14,1436.07 3075.14,1447.61 U2.3@3075.39,1447.87
  Bottom Layer w13: 3028.01,1419.47 3015.35,1406.81 3015.35,1234.29 v1(3036.94,1212.7)
PWDN_EXT: J14.55 J22.62 | length 957.3
  Top Layer w13: J14.55@78.74,1098.43 213.85,1098.43 311.04,1001.24 311.04,596.66 403.33,504.36 482.28,504.36 J22.62@532.28,454.36
PWDN_LVL: R10.1 U2.6 | length 1060.3
  Bottom Layer w6: 3072.87,1525.59 3075.39,1523.07 U2.6@3075.39,1489.76
  Bottom Layer w13: 3072.87,1525.59 3062.6,1535.87 3062.6,1600.14 2999.92,1662.82 2999.92,1953.07 3192.52,2145.67 3384.22,2145.67 R10.1@3456.12,2217.57
RBIAS: R48.2 U14.10 | length 166.8
  Top Layer w9: U14.10@3577.08,1291.5 3577.08,1334.65 v1(3581.01,1338.58)
  Bottom Layer w9: R48.2@3536.52,1438.22 3536.52,1383.07 v1(3581.01,1338.58)
RD_N: C97.1 R113.1 U14.4 | length 372.7
  Top Layer w9: U14.4@3622.31,1187.17 3622.73,1187.59 3630.46,1187.59 3630.89,1188.01 3694.38,1188.01 3750.06,1132.33 3918.3,1132.33 C97.1@3935.45,1115.18 R113.1@3964.48,1115.18
RD_N1: C98.1 R113.2 T2.8 U13.5 U13.6 | length 474.3
  Top Layer w9: R113.2@3999.91,1115.18 C98.1@4028.94,1115.18 4046.1,1132.33 4064.02,1132.33 4106.45,1174.77 4122.24,1174.77 4155.12,1174.77 4185.75,1174.77 4200.39,1160.12 4200.39,1106.68 4229.53,1077.54 4279.43,1077.54 4320.43,1036.54 T2.8@4360.97,1036.54
RD_P: C95.1 R112.1 U14.5 | length 372.4
  Top Layer w9: U14.5@3622.31,1206.85 3622.73,1206.43 3630.46,1206.43 3630.89,1206.01 3701.84,1206.01 3757.52,1150.33 3917.89,1150.33 C95.1@3935.04,1167.48 R112.1@3964.21,1167.48
RD_P1: C96.1 R112.2 T2.6 U13.4 U13.7 | length 474.6
  Top Layer w9: R112.2@3999.65,1167.48 C96.1@4028.94,1167.48 4046.1,1150.33 4056.56,1150.33 4099,1192.77 4185.75,1192.77 4193.2,1192.77 4218.39,1167.58 4218.39,1114.13 4236.99,1095.54 4280.26,1095.54 4321.26,1136.54 T2.6@4360.97,1136.54
RESET: C60.1 C88.1 J18.60 S3.2 U2.4 U14.32 | length 3150.9
  Top Layer w9: U14.32@3596.76,1102.52 3634.75,1064.53 v1(3634.75,1056.94)
  Top Layer w13: S3.2@2727.95,487.44 2727.95,425.43 C60.1@2716.29,413.77 2866.8,413.77 2957.11,323.47 v1(2957.11,322.38)
  Signal1 w13: v1(2957.11,322.38) 3014.83,380.1 3014.83,963.36 2930.35,1047.84 v1(2930.35,1444.33) 2947.54,1461.51 3095.14,1461.51 3165.75,1390.9 3266.28,1390.9 3281.23,1405.85 3304.94,1429.56 3378.25,1429.56 3379.81,1427.99 3400.66,1427.99 3605.13,1223.53 3605.13,1086.57 v1(3634.75,1056.94)
  Bottom Layer w6: v1(2930.35,1444.33) 2930.35,1472.09 2954.33,1496.06 3009.06,1496.06 3048.82,1456.3 3059.65,1456.3 U2.4@3061.61,1454.33
  Bottom Layer w13: v1(2957.11,322.38) 2958.19,322.38 3015.35,265.22 J18.60@3015.35,92.66 ; v1(3634.75,1056.94) 3634.75,1005.81 3660.64,979.92 C88.1@3660.64,948.8
RESET_EXT: J14.60 J22.59 | length 760.9
  Bottom Layer w13: J14.60@78.74,1035.43 118.05,1035.43 145.18,1008.3 145.18,823.83 366.97,602.04 484.6,602.04 J22.59@532.28,554.36
RESET_LVL: R11.1 U2.5 | length 1064.3
  Bottom Layer w6: 3052.76,1515.75 3061.61,1506.89 U2.5@3061.61,1489.76
  Bottom Layer w13: 3052.76,1515.75 3002.72,1565.78 2973.46,1565.78 2964.17,1575.07 2964.17,1978.35 3161.02,2175.2 3318.5,2175.2 R11.1@3376.74,2233.44
RST/SBWTDIO: C17.2 J3.3 R22.2 R95.2 S2.2 U8.76 | length 4746.4
  Top Layer w9: U8.76@3459.95,1874.25 3461.36,1875.65 3461.36,1913.01 3466.89,1918.54 ; C17.2@4314.08,1807.55 C17.2@4314.08,1812.24
  Top Layer w13: 3466.89,1918.54 3466.89,1975.77 ; v1(3466.89,2123.46) 3466.89,1975.77 ; C17.2@4314.08,1807.55 4314.08,1805.55 4224.42,1805.55 4222.42,1807.55 4079.1,1807.55 S2.2@4076.38,1810.27 4049.41,1837.24 3853.28,1837.24 3842.64,1847.87 3798.12,1847.87 3787.49,1837.24 3636.02,1837.24 3497.5,1975.77 3466.89,1975.77 ; C17.2@4314.08,1812.24 4319.99,1818.14 R22.2@4392.82,1818.14
  Signal1 w13: J3.3@1735.49,2539.4 1765.05,2509.84 3029.47,2509.84 3416,2123.31 3527.84,2122.08 3558.4,2152.64 4269.26,2152.64 4552.41,2435.79 4834.33,2435.79 v1(4847.52,2422.61)
  Bottom Layer w13: v1(4847.52,2422.61) 4857.39,2432.48 R95.2@4857.39,2478.66
RX_CLK: J18.30 R104.2 R114.2 R115.2 | length 1622.1
  Top Layer w13: v1(3273.04,1235.71) 3280.82,1243.5 3281.05,1243.27 3304.4,1243.27 R104.2@3322.05,1225.62
  Signal1 w13: v1(3273.04,1235.71) 3281.62,1244.29 3310.86,1244.29 3444.6,1110.56 3444.6,789.37 3444.6,777.55 cw(c3440.6,777.55) 3440.6,773.56 ccw(c3440.6,760.56) 3427.6,760.56 ccw(c3440.6,760.56) 3440.6,747.56 3444.6,747.56 3444.78,747.56 cw(c3444.78,734.56) 3457.78,734.56 cw(c3444.78,734.56) 3444.78,721.56 3444.6,721.56 3440.6,721.56 ccw(c3440.6,708.56) 3427.6,708.56 ccw(c3440.6,708.56) 3440.6,695.56 3444.6,695.56 3444.78,695.56 cw(c3444.78,682.56) 3457.78,682.56 cw(c3444.78,682.56) 3444.78,669.56 3444.6,669.56 3440.6,669.56 ccw(c3440.6,656.56) 3427.6,656.56 ccw(c3440.6,656.56) 3440.6,643.56 3444.6,643.56 3444.78,643.56 cw(c3444.78,630.56) 3457.78,630.56 cw(c3444.78,630.56) 3444.78,617.56 3444.6,617.56 3440.6,617.56 ccw(c3440.6,604.56) 3427.6,604.56 ccw(c3440.6,604.56) 3440.6,591.56 3444.6,591.56 3444.78,591.56 cw(c3444.78,578.56) 3457.78,578.56 cw(c3444.78,578.56) 3444.78,565.56 3444.6,565.56 3440.6,565.56 ccw(c3440.6,552.56) 3427.6,552.56 ccw(c3440.6,552.56) 3440.6,539.56 3444.6,539.56 3444.78,539.56 cw(c3444.78,526.56) 3457.78,526.56 cw(c3444.78,526.56) 3444.78,513.56 3444.6,513.56 3444.6,487.56 3444.6,474.56 3444.6,470.52 3487.8,427.32 v1@3487.8,346.46
  Bottom Layer w13: R114.2@3283.73,1279.05 3273.04,1268.36 v1(3273.04,1235.71) 3276.67,1239.34 3306.93,1239.34 3310.56,1235.71 R115.2@3338.19,1235.71 ; v1(3485.28,344.21) 3487.8,341.69 J18.30@3487.8,99.69
RX_CLK_EXT: J14.30 J22.29 | length 472.8
  Bottom Layer w13: J14.30@78.74,1507.87 485.79,1507.87 J22.29@532.28,1554.36
RX_D0: J18.26 R78.2 | length 1543.5
  Top Layer w13: v1(3292.16,1379.47) 3292.16,1376.83 3335.1,1333.89 R78.2@3412.12,1333.89
  Signal1 w13: v1(3292.16,1379.47) 3292.16,1292.52 3478.65,1106.03 3478.65,992.63 3479.13,992.15 3479.13,970.97 3478.65,970.49 3478.65,940.63 3479.13,940.15 3479.13,918.97 3478.65,918.49 3478.65,888.63 3479.13,888.15 3479.13,866.97 3478.65,866.49 3478.65,836.63 3479.13,836.15 3479.13,814.97 3478.65,814.49 3478.65,784.63 3479.13,784.15 3479.13,762.97 3478.65,762.49 3478.65,732.63 3479.13,732.15 3479.13,710.97 3478.65,710.49 3478.65,680.63 3479.13,680.15 3479.13,658.97 3478.65,658.49 3478.65,628.63 3479.13,628.15 3479.13,606.97 3478.65,606.49 3478.65,576.63 3479.13,576.15 3479.13,554.97 3478.65,554.49 3478.65,524.63 3479.13,524.15 3479.13,521.76 3548.84,452.05 3548.84,312.56 v1(3552,309.39)
  Bottom Layer w13: v1(3552,309.39) 3550.79,308.18 3550.79,285.9 3540.54,275.65 3540.54,155.01 3543.51,152.04 3543.51,127.37 3550.79,120.09 3550.79,102.14 J18.26@3554.72,98.2
RX_D0_EXT: J14.26 J22.26 | length 488.1
  Bottom Layer w13: J14.26@78.74,1570.87 361.07,1570.87 394.53,1604.33 482.25,1604.33 J22.26@532.28,1654.36
RX_D1: J18.24 R102.2 | length 1460.6
  Top Layer w13: v1(3372.68,1365.39) 3384.42,1365.39 3391.51,1372.47 R102.2@3418.61,1372.47
  Signal1 w13: v1@3367.8,1365.39 v1(3372.68,1365.39) 3393.78,1339.4 3408.95,1339.4 3424.4,1323.95 3424.4,1308.79 3472.15,1261.03 3472.15,1177.56 3517.32,1132.39 3517.32,985.03 3500.01,967.72 3500.01,962.33 3499.53,961.84 3499.53,949.28 3500.01,948.8 3500.01,910.33 3499.53,909.84 3499.53,897.28 3500.01,896.8 3500.01,858.33 3499.53,857.84 3499.53,845.28 3500.01,844.8 3500.01,806.33 3499.53,805.84 3499.53,793.28 3500.01,792.8 3500.01,754.33 3499.53,753.84 3499.53,741.28 3500.01,740.8 3500.01,702.33 3499.53,701.84 3499.53,689.28 3500.01,688.8 3500.01,655.05 3578.9,576.17 3578.9,396.05 3569.71,386.87 3569.71,328.98 3578.38,320.32 3578.38,305.84 v1@3588.94,295.28
  Bottom Layer w13: J18.24@3582.28,101.18 3582.28,118.11 3575,125.39 3575,152.04 3565.43,161.62 3563.45,161.62 3561.42,163.66 3561.42,267.01 v1(3589.41,294.99)
RX_D1_EXT: J14.24 J22.23 | length 516.5
  Bottom Layer w13: J14.24@78.74,1602.36 297.29,1602.36 397.69,1702.76 480.68,1702.76 J22.23@532.28,1754.36
RX_D2: J18.22 R101.2 | length 1629
  Top Layer w13: v1(3320.9,1403.18) 3327.39,1409.68 R101.2@3423.14,1409.68
  Signal1 w13: v1(3320.9,1403.18) 3395.95,1403.18 3584.25,1214.88 3584.25,1184.94 3538.19,1138.88 3538.19,976.38 3524.35,962.54 3524.35,771.99 3601.18,695.16 3601.18,408.14 3622.46,386.87 3622.46,331.48 v1(3615.78,324.8)
  Bottom Layer w13: J18.22@3613.78,101.18 3615.78,103.18 v1(3615.78,324.8)
RX_D2_EXT: J14.22 J22.20 | length 544.9
  Bottom Layer w13: J14.22@78.74,1633.86 234.81,1633.86 400.2,1799.25 477.17,1799.25 J22.20@532.28,1854.36
RX_D3: J18.20 R100.2 | length 1659.4
  Top Layer w13: v1(3390.74,1454.36) 3398.02,1447.08 R100.2@3429.63,1447.08
  Signal1 w13: v1(3390.74,1454.36) 3421.92,1454.36 3692.52,1183.77 3692.52,1087.15 3661.13,1055.76 3661.13,1046.01 3645.68,1030.56 3635.93,1030.56 3545.23,939.86 3545.23,780.63 3622.06,703.8 3622.06,416.79 3643.85,394.99 3643.85,343.41 ; v1@3643.82,275.88 3643.82,343.37
  Bottom Layer w13: J18.20@3643.15,87.13 v1(3643.15,275.31)
RX_D3_EXT: J14.20 J22.17 | length 573.3
  Bottom Layer w13: J14.20@78.74,1665.35 170.61,1665.35 409.59,1904.33 482.25,1904.33 J22.17@532.28,1954.36
RX_DV: J18.32 R103.2 | length 1546.8
  Top Layer w13: v1@3243.41,1222.15 v1(3243.41,1220.25) 3243.41,1245.56 3263.77,1265.91 R103.2@3296.06,1265.91
  Signal1 w13: v1(3243.41,1220.25) 3243.41,1206.24 3284.3,1165.35 3353.94,1165.35 3420.85,1098.45 3420.85,811 3390.74,780.9 3390.74,754.9 ccw(c3390.74,741.9) 3390.74,728.9 cw(c3390.74,715.9) 3390.74,702.9 ccw(c3390.74,689.9) 3390.74,676.9 cw(c3390.74,663.9) 3390.74,650.9 ccw(c3390.74,637.9) 3390.74,624.9 cw(c3390.74,611.9) 3390.74,598.9 ccw(c3390.74,585.9) 3390.74,572.9 cw(c3390.74,559.9) 3390.74,546.9 ccw(c3390.74,533.9) 3390.74,520.9 cw(c3390.74,507.9) 3390.74,494.9 ccw(c3390.74,481.9) 3390.74,468.9 3390.74,442.9 3390.74,441.55 3403.15,429.14 3452.63,379.66 v1@3452.63,305.12
  Bottom Layer w13: v1(3453.08,305.12) 3456.3,301.9 J18.32@3456.3,78.74
RX_DV_EXT: J14.32 J22.32 | length 505.1
  Bottom Layer w13: J14.32@78.74,1476.38 256,1476.38 329.2,1403.18 481.1,1403.18 J22.32@532.28,1454.36
RX_ER: J18.56 R99.2 | length 1546.6
  Top Layer w13: v1(3191.12,1181.1) R99.2@3291.54,1181.1
  Signal1 w13: v1(3094.61,292.23) 3101.97,299.58 3101.97,514.96 3129.92,542.92 3129.92,561.02 3129.92,585.89 ccw(c3128.91,585.89) 3128.91,586.91 cw(c3128.91,599.91) 3115.91,599.91 cw(c3128.91,599.91) 3128.91,612.91 3129.92,612.91 3130.93,612.91 ccw(c3130.93,625.91) 3143.93,625.91 ccw(c3130.93,625.91) 3130.93,638.91 3129.92,638.91 3128.91,638.91 cw(c3128.91,651.91) 3115.91,651.91 cw(c3128.91,651.91) 3128.91,664.91 3129.92,664.91 3130.93,664.91 ccw(c3130.93,677.91) 3143.93,677.91 ccw(c3130.93,677.91) 3130.93,690.91 3129.92,690.91 3128.91,690.91 cw(c3128.91,703.91) 3115.91,703.91 cw(c3128.91,703.91) 3128.91,716.91 3129.92,716.91 3130.93,716.91 ccw(c3130.93,729.91) 3143.93,729.91 ccw(c3130.93,729.91) 3130.93,742.91 3129.92,742.91 3128.91,742.91 cw(c3128.91,755.91) 3115.91,755.91 cw(c3128.91,755.91) 3128.91,768.91 3129.92,768.91 3130.93,768.91 ccw(c3130.93,781.91) 3143.93,781.91 ccw(c3130.93,781.91) 3130.93,794.91 3129.92,794.91 3128.91,794.91 cw(c3128.91,807.91) 3115.91,807.91 cw(c3128.91,807.91) 3128.91,820.91 3129.92,820.91 3130.93,820.91 ccw(c3130.93,833.91) 3143.93,833.91 ccw(c3130.93,833.91) 3130.93,846.91 3129.92,846.91 3128.91,846.91 cw(c3128.91,859.91) 3115.91,859.91 cw(c3128.91,859.91) 3128.91,872.91 3129.92,872.91 3130.93,872.91 ccw(c3130.93,885.91) 3143.93,885.91 ccw(c3130.93,885.91) 3130.93,898.91 3129.92,898.91 3128.91,898.91 cw(c3128.91,911.91) 3115.91,911.91 cw(c3128.91,911.91) 3128.91,924.91 3129.92,924.91 3130.93,924.91 ccw(c3130.93,937.91) 3143.93,937.91 ccw(c3130.93,937.91) 3130.93,950.91 3129.92,950.91 3128.91,950.91 cw(c3128.91,963.91) 3115.91,963.91 cw(c3128.91,963.91) 3128.91,976.91 3129.92,976.91 3130.93,976.91 ccw(c3130.93,989.91) 3143.93,989.91 ccw(c3130.93,989.91) 3130.93,1002.91 3129.92,1002.91 3128.91,1002.91 cw(c3128.91,1015.91) 3115.91,1015.91 cw(c3128.91,1015.91) 3128.91,1028.91 3129.92,1028.91 3130.93,1028.91 ccw(c3130.93,1041.91) 3143.93,1041.91 ccw(c3130.93,1041.91) 3130.93,1054.91 3129.92,1054.91 3128.91,1054.91 cw(c3128.91,1067.91) 3115.91,1067.91 cw(c3128.91,1067.91) 3128.91,1080.91 ccw(c3128.91,1081.92) 3129.92,1081.92 3129.92,1106.91 3129.92,1119.91 v1(3191.12,1181.1)
  Bottom Layer w13: J18.56@3078.35,101.18 3078.35,275.96 v1(3094.61,292.23)
RX_ER_EXT: J14.56 J22.35 | length 1449.7
  Bottom Layer w13: J14.56@78.74,1098.43 230.84,1098.43 305.28,1023.98 305.28,810.82 412.64,703.46 556.26,703.46 583.82,731.02 583.82,1302.83 J22.35@532.28,1354.36
RX_OPT: R6.1 R9.1 U9.4 | length 885.8
  Top Layer w13: R9.1@3015.35,2372.05 3025.2,2381.89 v1(3066.8,2381.89)
  Bottom Layer w13: v1(3066.8,2381.89) 3142.52,2381.89 3235.02,2289.39 3270.14,2289.39 3283.29,2276.24 U9.4@3283.29,2258.86 3308.7,2258.86 3381.21,2331.36 3381.21,2463.15 3438.04,2519.98 R6.1@3650.56,2519.98
SW1: S1.4 U8.77 | length 1784.2
  Top Layer w9: v1@2194.88,1629.56 v1(2196.46,1627.99) ; v1(3474.32,1822.08) 3479.64,1827.4 U8.77@3479.64,1873.69 U8.77@3479.64,1874.25
  Top Layer w13: S1.4@2102.36,1629.56 v1@2194.88,1629.56
  Signal1 w13: v1(2196.46,1627.99) 2196.46,1699.07 2603.37,2105.98 3190.42,2105.98 v1(3474.32,1822.08)
SW2: S1.3 U8.78 | length 1677.9
  Top Layer w9: v1@2191.7,1579.56 v1(2196.46,1574.8) ; v1(3492.63,1795.31) 3494.13,1795.31 3499.32,1800.5 U8.78@3499.32,1873.69 U8.78@3499.32,1874.25
  Top Layer w13: S1.3@2102.36,1579.56 v1@2191.7,1579.56
  Signal1 w13: v1(2196.46,1574.8) 2523.52,1901.87 2949.44,1901.87 2969.55,1881.76 3126.87,1881.76 3153.34,1908.23 3297.24,1908.23 3410.15,1795.31 v1(3492.63,1795.31) v1@3492.63,1793.81
SW3: S1.2 U8.79 | length 1713.1
  Top Layer w9: v1@2192.49,1529.56 v1(2196.46,1525.59) ; 3519.01,1809.38 U8.79@3519.01,1873.69 U8.79@3519.01,1874.25
  Top Layer w13: S1.2@2102.36,1529.56 v1@2192.49,1529.56 ; v1@3519.01,1773.31 3519.01,1809.38
  Signal1 w13: v1(2196.46,1525.59) 2471.62,1800.76 3107.34,1800.76 3175.35,1868.77 3282.57,1868.77 3392.57,1758.76 3505.03,1758.76 v1(3519.29,1773.02)
SW4: S1.1 U8.80 | length 1717.2
  Top Layer w9: v1@2193.27,1479.56 v1(2196.46,1476.38) ; 3538.69,1831.84 U8.80@3538.69,1874.25
  Top Layer w13: S1.1@2102.36,1479.56 v1@2193.27,1479.56 ; 3538.69,1831.84 v1(3554.92,1815.61)
  Signal1 w9: v1@3554.72,1815.41 v1(3554.92,1815.61)
  Signal1 w13: v1(2196.46,1476.38) 2485.48,1765.4 3108.73,1765.4 3142.07,1732.06 3522.31,1732.06 3554.72,1764.47 v1@3554.72,1815.41
Sys_5V: C31.1 C32.1 J6.2 J23.2 R27.2 U11.2 | length 3735.6
  Signal1 w50: J6.2@2671.4,1206.85 2859.95,1395.4 2859.95,1552.97 2985.59,1678.61 3586.1,1678.61 3667.61,1597.1 3979.77,1597.1 4065.3,1682.63 4065.3,1870.76 4141.9,1947.36 4498.82,1947.36 4586.57,1859.61 5008.62,1859.61 5128.44,1979.43 5128.44,2139.64 5283.21,2294.41 J23.2@5512.8,2294.41
  Bottom Layer w25: C32.1@2830.23,1246.22 C32.1@2835.26,1241.19
TARGET_D_N: C71.2 R63.1 U8.64 | length 657.3
  Top Layer w9: U8.64@3223.73,1874.25 3223.73,1837.81 3228.42,1833.12 3228.42,1812.92 3213.04,1797.55 3213.04,1782.02 v1(3225.5,1769.56)
  Bottom Layer w9: v1(3225.5,1769.56) 3219.42,1763.48 3219.42,1762.52 3210.51,1753.61 3210.51,1711.12 3209.89,1710.51 3209.89,1696.58 C71.2@3235.34,1671.14 3209.89,1645.69 3209.89,1612.08 3232.04,1589.94 3512.48,1589.94 3528.09,1605.55 R63.1@3548.34,1605.55
TARGET_D_P: C70.2 R20.2 R66.1 U8.62 | length 695.2
  Top Layer w9: U8.62@3184.36,1874.25 3184.36,1837.81 3179.67,1833.12 3179.67,1812.92 3185.63,1806.97 v1(3185.63,1777.12)
  Bottom Layer w9: v1(3185.63,1777.12) 3190.55,1777.12 3191.89,1775.77 3191.89,1696.58 C70.2@3166.45,1671.14 3191.89,1645.69 3191.89,1604.63 ; 3191.89,1604.62 3224.58,1571.94 3512.48,1571.94 3528.09,1556.33 R66.1@3548.34,1556.33 3543.84,1560.83 3532.02,1560.83
TARGET_PUR: R20.1 R21.1 U8.63 | length 197.9
  Top Layer w9: v1(3204.04,1823.02) U8.63@3204.04,1874.25
  Bottom Layer w13: R20.1@3126.57,1729.53 R21.1@3126.57,1781.5 3168.1,1823.02 v1(3204.04,1823.02)
TD_CH1_N: J17.2 T2.14 | length 634.9
  Top Layer w9: T2.14@4696.01,1286.54 4741.04,1286.54 4782.04,1327.54 5036.32,1327.54 5089.73,1327.54 5236.58,1327.54 5255.39,1308.72 5255.39,1293.6 J17.2@5230.18,1268.39
TD_CH1_P: J17.1 T2.16 | length 636.6
  Top Layer w9: T2.16@4696.01,1386.54 4737.03,1386.54 4778.03,1345.54 5242.58,1345.54 5279.56,1308.55 J17.1@5300.26,1308.55
TD_CH2_N: J17.6 T2.9 | length 675.1
  Top Layer w9: T2.9@4696.01,1036.54 4736.58,1036.54 4777.58,1077.54 4889.57,1077.54 5020.61,1208.57 5176.97,1208.57 5189.13,1196.41 5189.13,1148.81 J17.6@5230.18,1107.76
TD_CH2_P: J17.3 T2.11 | length 676.2
  Top Layer w9: T2.11@4696.01,1136.54 4737.03,1136.54 4778.03,1095.54 4882.12,1095.54 5014.81,1228.24 J17.3@5300.26,1228.24
TD_N: C93.1 R111.1 U14.6 | length 364.9
  Top Layer w9: U14.6@3622.31,1226.54 3622.73,1226.96 3630.46,1226.96 3630.89,1227.38 3836.84,1227.38 3875.79,1266.33 3917.49,1266.33 C93.1@3934.63,1249.18 R111.1@3963.66,1249.18
TD_N1: C94.1 R111.2 T2.3 U13.2 U13.9 | length 470.9
  Top Layer w9: R111.2@3999.09,1249.18 C94.1@4028.12,1249.18 4044.46,1265.52 4066.52,1265.52 4098.39,1233.65 4192.73,1233.65 4213.41,1254.33 4213.41,1311.01 4229.94,1327.54 4278.48,1327.54 4319.48,1286.54 T2.3@4360.97,1286.54
TD_P: C89.1 R52.1 U14.7 | length 364.6
  Top Layer w9: U14.7@3622.31,1246.22 3622.73,1245.8 3630.46,1245.8 3630.89,1245.38 3829.39,1245.38 3868.33,1284.33 3917.28,1284.33 C89.1@3934.22,1301.26 ; C89.1@3934.22,1301.48 R52.1@3963.39,1301.48
TD_P1: C92.1 R52.2 T2.1 U13.1 U13.10 | length 471.9
  Top Layer w9: R52.2@3998.82,1301.48 C92.1@4028.12,1301.48 4046.09,1283.52 4073.98,1283.52 4105.85,1251.65 4185.27,1251.65 4195.41,1261.79 4195.41,1318.47 4222.48,1345.54 4281.87,1345.54 4322.87,1386.54 T2.1@4360.97,1386.54
TEST/SBWTCK: J3.1 R94.2 U8.71 | length 3704.1
  Top Layer w9: 3360.12,1902.62 3361.04,1903.54 3361.04,1920.11 3367.27,1929.13 ; U8.71@3361.52,1874.25 3362.93,1875.65 3362.93,1903.9
  Top Layer w13: 3367.27,1929.13 v1(3368.46,2057.09)
  Signal1 w13: J3.1@1635.49,2539.4 1697.3,2477.59 2919.88,2477.59 3340.39,2057.09 v1(3368.46,2057.09) 4388.08,2057.09 4732.57,2401.57 v1(4735.82,2401.57)
  Bottom Layer w9: v1(4735.82,2401.57) v1@4735.82,2404.82
  Bottom Layer w13: v1@4735.82,2404.82 4753.61,2422.61 R94.2@4799.52,2422.61
TX_CLK: J18.36 R98.2 | length 1215.7
  Top Layer w13: v1(3278.45,1130.17) 3275.42,1127.13 R98.2@3314.4,1127.13
  Signal1 w13: v1(3278.45,1130.17) 3359.61,1130.17 3396.56,1093.21 3396.56,860.19 3347.34,810.97 3347.34,403.77 3366.17,384.94 3366.17,363.09 3361.07,357.99 3361.07,289.68 v1@3370.87,279.88
  Bottom Layer w13: v1(3370.2,282.91) 3393.31,259.8 J18.36@3393.31,101.18
TX_CLK_EXT: J14.36 J22.53 | length 941.1
  Top Layer w13: v1(165.87,1413.39) 367.11,1212.15 367.11,845.82 409.78,803.15 483.5,803.15 J22.53@532.28,754.36
  Bottom Layer w13: J14.36@78.74,1413.39 v1(165.87,1413.39)
TX_D0: J18.46 U14.24 | length 1183.2
  Top Layer w9: 3366.64,1064.34 3412.12,1078 3433.38,1099.26 U14.24@3433.38,1128.11
  Top Layer w13: v1(3303.06,1048.89) 3351.19,1048.89 3366.64,1064.34
  Signal1 w13: v1@3210.24,279.88 3210.51,280.15 3210.51,956.34 v1(3303.06,1048.89)
  Bottom Layer w13: v1(3209.32,277) 3215.88,270.45 3215.88,264.38 3235.83,244.43 J18.46@3235.83,88.58
TX_D0_EXT: J14.46 J22.50 | length 694.2
  Bottom Layer w13: J14.46@78.74,1255.91 176.61,1255.91 343.54,1088.98 343.54,962.15 400.3,905.39 481.26,905.39 J22.50@532.28,854.36
TX_D1: J18.44 U14.25 | length 1156.5
  Top Layer w9: 3458.97,1082.68 U14.25@3458.97,1102.52
  Top Layer w13: v1(3330.32,1013.78) 3357.17,1013.78 3379.91,1036.51 3426.98,1036.51 3458.97,1068.5 3458.97,1082.68
  Signal1 w13: v1@3243.41,275.59 3243.7,275.88 3243.7,927.17 v1(3330.32,1013.78)
  Bottom Layer w13: v1(3242.25,275.31) 3242.25,267.53 3256.7,253.08 3256.7,207.16 3267.01,196.85 J18.44@3267.01,88.58
TX_D1_EXT: J14.44 J22.47 | length 634.7
  Bottom Layer w13: J14.44@78.74,1287.4 194.13,1287.4 377.29,1104.24 377.29,1030.44 408.48,999.25 487.4,999.25 J22.47@532.28,954.36
TX_D2: J18.42 U14.26 | length 1132.3
  Top Layer w9: 3478.65,1069.41 U14.26@3478.65,1102.52
  Top Layer w13: v1(3339.19,956.72) 3376.71,956.72 3479.84,1059.85 3479.84,1069.41
  Signal1 w13: v1@3292.85,305.12 3290.95,307.02 3290.95,327.38 3288.72,329.61 3288.72,817.5 3290.95,819.73 3290.95,917.32 3330.34,956.72 v1(3339.19,956.72)
  Bottom Layer w13: v1(3293.48,304.84) 3311.02,287.3 3311.02,156.97 3306.1,152.04 3306.1,125.39 3302.95,122.24 J18.42@3302.95,88.58
TX_D2_EXT: J14.42 J22.44 | length 563.1
  Bottom Layer w13: J14.42@78.74,1318.9 197.29,1318.9 411.82,1104.36 482.28,1104.36 J22.44@532.28,1054.36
